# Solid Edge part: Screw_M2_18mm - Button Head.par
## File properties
Author: hhakima
Template: Normal.par
Last saved by: hhakima
Revision: 3
Application: Solid Edge
Material: Stainless steel
Face Style: Steel
Fill Style: ANSI32(Steel)
Virtual Style: Stainless steel
Coef. of Thermal Exp: 1.6e-05
Thermal Conductivity: 17.0
Specific Heat: 502.0
Modulus of Elasticity: 193053196000.0
Poission's Ratio: 0.29
Yield Stress: 310264065.0
Ultimate Stress: 641212401.0
Elongation: 0.0
Density: 7750.000 kg/m^3
Accuracy: 0.990
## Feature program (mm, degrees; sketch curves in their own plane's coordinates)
body "unnamed Body 1"
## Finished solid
Body 1: solid body, 33 faces, 80 edges, 50 vertices.
  Faces by surface: plane 19, cone 5, cylinder 3, spline 3, torus 2, sphere 1
  Edges by curve: circle 33, line 29, intersection 13, spline 5
Bounding box of the edges (mm; curved faces can reach further): 4.000 x 4.000 x 19.610, from (-2, -2, 0) to (2, 2, 19.6098).
Cylindrical faces by radius (mm): R0.7402 x1, R1 x1, R2 x1
Conical faces (half-angle, radius in mm at the cone's reference point): 15 deg R1.5 x4, 45 deg R3.9152 x1
Toroidal faces (ring radius, tube radius in mm): R1.694 r0.306 x2
Spherical faces by radius (mm): R2.7779 x1
Planar faces by outward normal: +z 1, -z 2, oblique 16
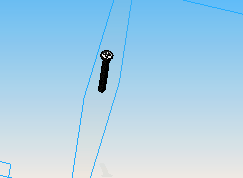
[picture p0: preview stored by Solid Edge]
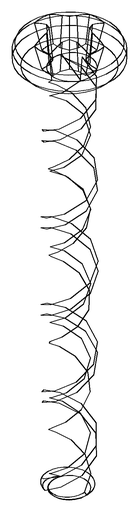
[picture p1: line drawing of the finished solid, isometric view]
